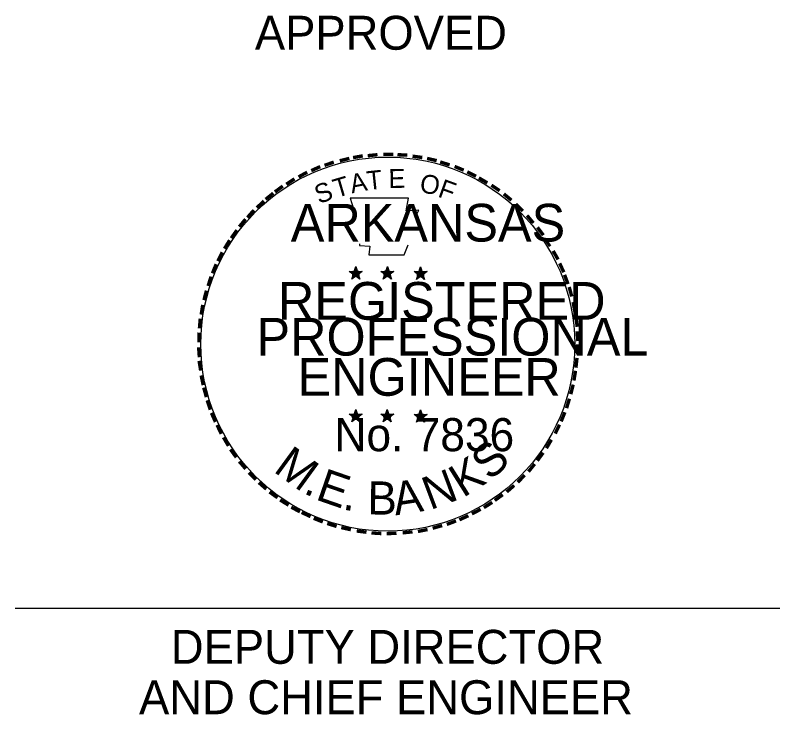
# Model space of a CAD drawing. Extents: x 1373862 to 1377080, y 1164775 to 1170415.
# Drawn here: x 1376517.3 to 1376911.7, y 1164775.4 to 1165136 of the extents above; entities that cross this region are included whole.
import ezdxf

# ---------------------------------------------------------------- set-up
doc = ezdxf.new("R2010")
doc.units = 0
doc.layers.add('R_Border PE', color=7, linetype='Continuous')

msp = doc.modelspace()

# ---------------------------------------------------------------- linework, layer by layer
at = {"layer": 'R_Border PE'}
for p, q in [((1376689.61, 1165003.97), (1376693.01, 1165002.87)), ((1376689.61, 1165003.97), (1376692.11, 1165003.57)), ((1376689.61, 1165003.97), (1376691.91, 1165002.77)), ((1376690.91, 1164999.97), (1376693.01, 1165002.87)), ((1376693.01, 1165006.47), (1376692.61, 1165003.97)), ((1376693.01, 1165002.87), (1376693.01, 1165006.47)), ((1376693.01, 1165006.47), (1376693.51, 1165004.07)), ((1376696.31, 1165003.97), (1376693.01, 1165002.87)), ((1376695.11, 1164999.97), (1376693.01, 1165002.87)), ((1376696.31, 1165003.97), (1376693.61, 1165003.47)), ((1376695.11, 1164999.97), (1376693.71, 1165002.77)), ((1376696.31, 1165003.97), (1376694.41, 1165002.97)), ((1376705.91, 1165003.97), (1376709.31, 1165002.87)), ((1376705.91, 1165003.97), (1376708.31, 1165003.57)), ((1376705.91, 1165003.97), (1376708.11, 1165002.77)), ((1376707.11, 1164999.97), (1376709.31, 1165002.87)), ((1376709.31, 1165006.47), (1376708.91, 1165003.97)), ((1376709.31, 1165002.87), (1376709.31, 1165006.47)), ((1376709.31, 1165006.47), (1376709.71, 1165004.07)), ((1376712.61, 1165003.97), (1376709.31, 1165002.87)), ((1376711.31, 1164999.97), (1376709.31, 1165002.87)), ((1376712.61, 1165003.97), (1376709.81, 1165003.47)), ((1376711.31, 1164999.97), (1376709.91, 1165002.77)), ((1376712.61, 1165003.97), (1376710.61, 1165002.97)), ((1376723.01, 1165003.87), (1376726.41, 1165002.77)), ((1376723.01, 1165003.87), (1376725.41, 1165003.37)), ((1376723.01, 1165003.87), (1376725.31, 1165002.67)), ((1376724.21, 1164999.87), (1376726.41, 1165002.77)), ((1376726.41, 1165006.27), (1376726.01, 1165003.87)), ((1376726.41, 1165002.77), (1376726.41, 1165006.27)), ((1376726.41, 1165006.27), (1376726.81, 1165003.87)), ((1376729.81, 1165003.87), (1376726.41, 1165002.77)), ((1376728.41, 1164999.87), (1376726.41, 1165002.77)), ((1376729.81, 1165003.87), (1376726.91, 1165003.37)), ((1376729.81, 1165003.87), (1376727.71, 1165002.87)), ((1376690.91, 1164999.97), (1376692.11, 1165002.37)), ((1376690.91, 1164999.97), (1376692.91, 1165002.07)), ((1376695.11, 1164999.97), (1376692.91, 1165002.07)), ((1376707.11, 1164999.97), (1376708.41, 1165002.37)), ((1376707.11, 1164999.97), (1376709.21, 1165002.07)), ((1376711.31, 1164999.97), (1376709.21, 1165002.07)), ((1376724.21, 1164999.87), (1376725.51, 1165002.27)), ((1376724.21, 1164999.87), (1376726.41, 1165001.97)), ((1376728.41, 1164999.87), (1376726.41, 1165001.97)), ((1376728.41, 1164999.87), (1376727.11, 1165002.67)), ((1376692.91, 1164932.77), (1376692.51, 1164930.37)), ((1376692.91, 1164929.27), (1376692.91, 1164932.77)), ((1376692.91, 1164932.77), (1376693.41, 1164930.37)), ((1376709.21, 1164932.77), (1376708.81, 1164930.37)), ((1376709.21, 1164929.27), (1376709.21, 1164932.77)), ((1376709.21, 1164932.77), (1376709.61, 1164930.37)), ((1376726.41, 1164932.67), (1376726.01, 1164930.27)), ((1376726.41, 1164929.17), (1376726.41, 1164932.67)), ((1376726.41, 1164932.67), (1376726.81, 1164930.27)), ((1376689.51, 1164930.37), (1376692.91, 1164929.27)), ((1376689.51, 1164930.37), (1376692.11, 1164929.87)), ((1376689.51, 1164930.37), (1376691.91, 1164929.17)), ((1376690.91, 1164926.37), (1376692.91, 1164929.27)), ((1376690.91, 1164926.37), (1376692.11, 1164928.77)), ((1376690.91, 1164926.37), (1376692.91, 1164928.57)), ((1376696.31, 1164930.37), (1376692.91, 1164929.27)), ((1376695.11, 1164926.37), (1376692.91, 1164929.27)), ((1376695.11, 1164926.37), (1376692.91, 1164928.47)), ((1376696.31, 1164930.37), (1376693.51, 1164929.87)), ((1376695.11, 1164926.37), (1376693.71, 1164929.17)), ((1376696.31, 1164930.37), (1376694.41, 1164929.37)), ((1376705.81, 1164930.37), (1376709.21, 1164929.27)), ((1376705.81, 1164930.37), (1376708.31, 1164929.87)), ((1376705.81, 1164930.37), (1376708.11, 1164929.17)), ((1376707.11, 1164926.37), (1376709.21, 1164929.27)), ((1376707.11, 1164926.37), (1376708.31, 1164928.77)), ((1376707.11, 1164926.37), (1376709.21, 1164928.57)), ((1376712.61, 1164930.37), (1376709.21, 1164929.27)), ((1376711.21, 1164926.37), (1376709.21, 1164929.27)), ((1376711.21, 1164926.37), (1376709.21, 1164928.47)), ((1376712.61, 1164930.37), (1376709.71, 1164929.87)), ((1376711.21, 1164926.37), (1376709.91, 1164929.17)), ((1376712.61, 1164930.37), (1376710.51, 1164929.37)), ((1376723.01, 1164930.27), (1376726.41, 1164929.17)), ((1376723.01, 1164930.27), (1376725.41, 1164929.77)), ((1376723.01, 1164930.27), (1376725.31, 1164929.07)), ((1376724.21, 1164926.27), (1376726.41, 1164929.17)), ((1376724.21, 1164926.27), (1376725.51, 1164928.67)), ((1376724.21, 1164926.27), (1376726.41, 1164928.47)), ((1376729.81, 1164930.27), (1376726.41, 1164929.17)), ((1376728.41, 1164926.27), (1376726.41, 1164929.17)), ((1376728.41, 1164926.27), (1376726.41, 1164928.37)), ((1376729.81, 1164930.27), (1376726.91, 1164929.77)), ((1376728.41, 1164926.27), (1376727.01, 1164929.07)), ((1376729.81, 1164930.27), (1376727.71, 1164929.27)), ((1376517.3, 1164830.4), (1376911.65, 1164830.4))]:
    msp.add_line(p, q, dxfattribs=at)
for points in [[(1376690.01, 1165041.67), (1376692.61, 1165033.57)], [(1376724.11, 1165032.77), (1376725.51, 1165035.47), (1376718.91, 1165035.27), (1376720.21, 1165041.67), (1376690.01, 1165041.67)], [(1376694.81, 1165018.17), (1376694.81, 1165017.27), (1376700.21, 1165017.07), (1376699.71, 1165012.47), (1376717.91, 1165012.47), (1376719.91, 1165017.67)], [(1376693.01, 1165006.47), (1376695.11, 1164999.97), (1376689.61, 1165003.97), (1376696.31, 1165003.97), (1376690.91, 1164999.97), (1376693.01, 1165006.47)], [(1376709.31, 1165006.47), (1376711.31, 1164999.97), (1376705.91, 1165003.97), (1376712.61, 1165003.97), (1376707.11, 1164999.97), (1376709.31, 1165006.47)], [(1376726.41, 1165006.27), (1376728.41, 1164999.87), (1376723.01, 1165003.87), (1376729.81, 1165003.87), (1376724.21, 1164999.87), (1376726.41, 1165006.27)], [(1376692.91, 1164932.77), (1376695.11, 1164926.37), (1376689.51, 1164930.37), (1376696.31, 1164930.37), (1376690.91, 1164926.37), (1376692.91, 1164932.77)], [(1376709.21, 1164932.77), (1376711.21, 1164926.37), (1376705.81, 1164930.37), (1376712.61, 1164930.37), (1376707.11, 1164926.37), (1376709.21, 1164932.77)], [(1376726.41, 1164932.67), (1376728.41, 1164926.27), (1376723.01, 1164930.27), (1376729.81, 1164930.27), (1376724.21, 1164926.27), (1376726.41, 1164932.67)]]:
    msp.add_lwpolyline(points, dxfattribs=at)
for centre, radius in [((1376709.45, 1164966.48), 96.45), ((1376692.92, 1165002.85), 1.67), ((1376692.92, 1165002.85), 1.41), ((1376692.92, 1165002.85), 1.13), ((1376692.92, 1165002.85), 0.963), ((1376692.92, 1165002.85), 0.726), ((1376692.92, 1165002.85), 0.482), ((1376692.92, 1165002.85), 0.288), ((1376709.16, 1165002.85), 1.67), ((1376709.16, 1165002.85), 1.41), ((1376709.16, 1165002.85), 1.13), ((1376709.16, 1165002.85), 0.963), ((1376709.16, 1165002.85), 0.726), ((1376709.16, 1165002.85), 0.482), ((1376709.16, 1165002.85), 0.288), ((1376726.3, 1165002.74), 1.67), ((1376726.3, 1165002.74), 1.41), ((1376726.3, 1165002.74), 1.13), ((1376726.3, 1165002.74), 0.963), ((1376726.3, 1165002.74), 0.726), ((1376726.3, 1165002.74), 0.482), ((1376726.3, 1165002.74), 0.288), ((1376692.88, 1164929.24), 1.67), ((1376692.88, 1164929.24), 1.41), ((1376692.88, 1164929.24), 1.13), ((1376692.88, 1164929.24), 0.963), ((1376692.88, 1164929.24), 0.726), ((1376692.88, 1164929.24), 0.482), ((1376692.88, 1164929.24), 0.288), ((1376709.11, 1164929.24), 1.67), ((1376709.11, 1164929.24), 1.41), ((1376709.11, 1164929.24), 1.13), ((1376709.11, 1164929.24), 0.963), ((1376709.11, 1164929.24), 0.726), ((1376709.11, 1164929.24), 0.482), ((1376709.11, 1164929.24), 0.288), ((1376726.28, 1164929.15), 1.67), ((1376726.28, 1164929.15), 1.41), ((1376726.28, 1164929.15), 1.13), ((1376726.28, 1164929.15), 0.963), ((1376726.28, 1164929.15), 0.726), ((1376726.28, 1164929.15), 0.482), ((1376726.28, 1164929.15), 0.288)]:
    msp.add_circle(centre, radius, dxfattribs=at)

# ---------------------------------------------------------------- texts
for s, height, p in [('APPROVED', 17.496, (1376640.91, 1165118.27)), ('ARKANSAS', 19.44, (1376659.41, 1165019.37)), ('REGISTERED', 19.44, (1376652.81, 1164979.07)), ('PROFESSIONAL', 19.44, (1376641.71, 1164960.57)), ('ENGINEER', 19.44, (1376662.91, 1164939.87)), ('No. 7836', 17.078, (1376681.98, 1164911.27)), ('DEPUTY DIRECTOR', 17.496, (1376597.54, 1164801.66)), ('AND CHIEF ENGINEER', 17.496, (1376581.14, 1164775.67))]:
    msp.add_text(s, height=height, dxfattribs=at).set_placement(p)
for s, height, rotation, p in [('-', 15.55, 13.6301, (1376685.21, 1165054.97)), ('-', 15.55, 10.2193, (1376691.71, 1165056.57)), ('-', 15.55, 5.8968, (1376698.81, 1165057.57)), ('-', 15.55, 0.1862, (1376706.31, 1165058.27)), ('-', 15.55, 357.743, (1376713.31, 1165058.17)), ('-', 15.55, 352.1617, (1376720.51, 1165057.57)), ('-', 15.55, 347.2049, (1376727.51, 1165056.57)), ('-', 15.55, 24.3072, (1376671.61, 1165050.07)), ('-', 15.55, 19.1761, (1376677.91, 1165052.67)), ('-', 15.55, 342.3362, (1376733.81, 1165054.97)), ('-', 15.55, 337.8551, (1376740.81, 1165052.87)), ('-', 15.55, 28.7918, (1376665.51, 1165046.97)), ('A', 9.72, 11.2132, (1376690.91, 1165044.17)), ('T', 9.72, 6.0228, (1376699.11, 1165045.87)), ('E', 9.72, 0.8323, (1376709.91, 1165046.97)), ('O', 9.72, 350.4515, (1376725.51, 1165044.87)), ('-', 15.55, 334.1211, (1376747.01, 1165050.27)), ('-', 15.55, 34.0636, (1376659.71, 1165043.37)), ('T', 9.72, 16.4036, (1376682.91, 1165041.77)), ('F', 9.72, 340.0707, (1376734.81, 1165042.67)), ('-', 15.55, 329.6409, (1376752.61, 1165047.47)), ('-', 15.55, 36.2317, (1376654.01, 1165039.57)), ('S', 9.72, 21.594, (1376674.01, 1165038.57)), ('-', 15.55, 325.8627, (1376758.81, 1165043.97)), ('-', 15.55, 38.9507, (1376649.51, 1165035.87)), ('-', 15.55, 320.5297, (1376764.81, 1165039.87)), ('-', 15.55, 42.9622, (1376645.31, 1165031.77)), ('-', 15.55, 315.5786, (1376770.61, 1165035.07)), ('-', 15.55, 48.4231, (1376640.91, 1165027.07)), ('-', 15.55, 50.6142, (1376636.91, 1165022.47)), ('-', 15.55, 309.8797, (1376776.11, 1165029.67)), ('-', 15.55, 306.6522, (1376781.31, 1165023.87)), ('-', 15.55, 54.2325, (1376633.01, 1165016.87)), ('-', 15.55, 58.0706, (1376629.81, 1165011.77)), ('-', 13.61, 303.6753, (1376785.91, 1165018.37)), ('-', 15.55, 299.6684, (1376789.11, 1165012.37)), ('-', 15.55, 62.8713, (1376626.71, 1165005.77)), ('-', 15.55, 67.7743, (1376624.21, 1164999.87)), ('-', 15.55, 294.6628, (1376792.31, 1165006.47)), ('-', 15.55, 72.3945, (1376622.21, 1164993.77)), ('-', 15.55, 290.5728, (1376794.71, 1165000.97)), ('-', 15.55, 285.1233, (1376797.01, 1164995.27)), ('-', 15.55, 75.461, (1376620.21, 1164986.77)), ('-', 15.55, 280.5493, (1376799.01, 1164987.97)), ('-', 15.55, 81.2013, (1376619.01, 1164979.87)), ('-', 15.55, 85.1863, (1376618.21, 1164973.17)), ('-', 15.55, 276.5962, (1376800.51, 1164980.67)), ('-', 15.55, 89.0622, (1376618.01, 1164966.37)), ('-', 15.55, 274.3301, (1376801.11, 1164973.57)), ('-', 15.55, 94.1959, (1376618.31, 1164959.27)), ('-', 15.55, 269.9407, (1376801.41, 1164967.37)), ('-', 15.55, 263.5172, (1376801.21, 1164960.97)), ('-', 15.55, 98.9479, (1376619.01, 1164952.87)), ('-', 15.55, 260.9953, (1376800.51, 1164954.57)), ('-', 15.55, 101.7149, (1376620.31, 1164945.67)), ('-', 15.55, 105.4578, (1376621.91, 1164939.87)), ('-', 15.55, 255.7626, (1376799.51, 1164947.97)), ('-', 15.55, 109.0874, (1376623.91, 1164933.77)), ('-', 15.55, 252.8681, (1376797.71, 1164940.97)), ('-', 15.55, 114.0643, (1376626.41, 1164927.97)), ('-', 15.55, 247.8887, (1376795.61, 1164934.47)), ('-', 15.55, 115.7289, (1376629.41, 1164921.97)), ('-', 15.55, 244.6197, (1376793.01, 1164928.37)), ('-', 15.55, 120.4471, (1376632.91, 1164916.27)), ('S', 17.08, 42.9205, (1376762.33, 1164895.61)), ('-', 15.55, 239.0712, (1376789.21, 1164921.07)), ('-', 15.55, 125.8934, (1376636.71, 1164910.87)), ('M', 17.08, 323.9056, (1376649.95, 1164901.06)), ('K', 17.08, 32.2382, (1376748.27, 1164887.03)), ('-', 15.55, 233.8452, (1376785.31, 1164914.77)), ('-', 15.55, 130.7181, (1376641.31, 1164905.37)), ('-', 15.55, 231.2538, (1376781.11, 1164909.17)), ('-', 15.55, 134.2238, (1376646.31, 1164900.17)), ('E', 17.08, 340.8881, (1376671.65, 1164886.54)), ('N', 17.08, 20.5042, (1376731.31, 1164880.8)), ('A', 17.08, 8.7702, (1376713.42, 1164878.14)), ('-', 15.55, 225.7653, (1376776.41, 1164903.77)), ('-', 15.55, 138.9338, (1376651.41, 1164895.67)), ('B', 17.08, 359.3149, (1376698.86, 1164878.69)), ('-', 15.55, 221.0851, (1376771.41, 1164898.77)), ('-', 15.55, 144.6463, (1376656.81, 1164891.67)), ('.', 17.08, 336.3407, (1376665.43, 1164889.79)), ('-', 15.55, 215.7363, (1376766.01, 1164894.27)), ('-', 15.55, 148.0898, (1376662.21, 1164888.07)), ('-', 15.55, 212.2491, (1376760.91, 1164890.47)), ('-', 15.55, 151.5704, (1376667.81, 1164884.87)), ('-', 15.55, 154.6002, (1376673.01, 1164882.57)), ('.', 17.08, 350.694, (1376685.82, 1164881.27)), ('-', 15.55, 207.3568, (1376755.41, 1164887.07)), ('-', 15.55, 158.5612, (1376679.01, 1164880.07)), ('-', 15.55, 204.2516, (1376749.41, 1164883.87)), ('-', 15.55, 162.7983, (1376685.71, 1164877.97)), ('-', 15.55, 167.5555, (1376692.61, 1164876.47)), ('-', 15.55, 195.4743, (1376736.81, 1164878.97)), ('-', 15.55, 200.7184, (1376743.41, 1164881.27)), ('-', 15.55, 173.1155, (1376700.11, 1164875.37)), ('-', 15.55, 176.5183, (1376707.41, 1164874.77)), ('-', 15.55, 181.5918, (1376714.71, 1164874.97)), ('-', 15.55, 185.8167, (1376722.51, 1164875.77)), ('-', 15.55, 191.2858, (1376729.71, 1164876.97))]:
    msp.add_text(s, height=height, rotation=rotation, dxfattribs=at).set_placement(p)

doc.saveas('drawing.dxf')
